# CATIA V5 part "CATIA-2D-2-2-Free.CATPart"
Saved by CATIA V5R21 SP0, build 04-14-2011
Part number: CATIA-2D-2-2-Free
Bounding box of the stored display mesh (mm): x -86.992 to 39.598, y 0 to 0, z -27 to 109
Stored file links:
  C:\Users\Rasoul Mohammadi\Desktop\CATIA-Free\2D\CATIA-2D-2-2-Free.CATPart
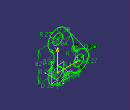
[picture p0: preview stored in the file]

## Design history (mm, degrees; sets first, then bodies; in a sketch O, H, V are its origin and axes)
Body1 (main body)
  Sketch1 on zx-plane, origin (0, 0, 0), H (-1, 0, 0), V (0, 0, 1)
    arc A1 centre (0, 0) radius 27 from (-18.7569, 19.4211) to (21.8919, -15.8033) ccw
    arc A2 centre (0, 82) radius 27 from (18.7569, 101.4211) to (-18.7569, 62.5789) ccw
    point P1 (0, 82)
    arc A3 centre (60, 0) radius 27 from (38.1081, -15.8033) to (55.8384, 26.6773) ccw
    point P2 (60, 0)
    arc A4 centre (-39.598, 41) radius 30 from (-18.7569, 62.5789) to (-18.7569, 19.4211) cw
    point P5 (-18.7569, 19.4211)
    arc A5 centre (30, -21.6564) radius 10 from (21.8919, -15.8033) to (38.1081, -15.8033) cw
    point P10 (44.3082, 37.0304)
    arc A6 centre (54.297, 36.5578) radius 10 from (44.3082, 37.0304) to (55.8384, 26.6773) ccw
    point P13 (-18.7569, 19.4211)
    line L1 (60, -27) -> (0, -27)
    point P14 (60, -27)
    point P15 (0, -27)
    line L2 (27.6064, 91.4254) -> (81.9337, 15.7452)
    point P17 (81.9337, 15.7452)
    arc A7 centre (-39.598, 41) radius 84 from (44.3082, 37.0304) to (18.7569, 101.4211) ccw
    point P18 (44.3082, 37.0304)
    circle A8 centre (0, 82) radius 14
    circle A9 centre (60, 0) radius 14
    point P19 (60, 0)
    circle A10 centre (0, 0) radius 14
    radius A1 = 27
    radius A3 = 27
    radius A2 = 27
    radius A4 = 30
    distance P2 V = 60
    radius A6 = 10
    radius A5 = 10
    distance H P1 = 82
    radius A7 = 84
    radius A9 = 14
    radius A8 = 14
    radius A10 = 14
    coincidence: P1 V, P2 H, P5 A1, A4 P13, P14 A3, P15 A1, P17 A3, P18 P10, P19 H
    tangency: A4 A2, A5 A1, A5 A3, A6 A3, A1 A4, L1 A1, L1 A3, L2 A3, L2 A7, A6 A7
    concentricity: A9 A3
